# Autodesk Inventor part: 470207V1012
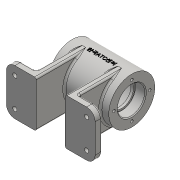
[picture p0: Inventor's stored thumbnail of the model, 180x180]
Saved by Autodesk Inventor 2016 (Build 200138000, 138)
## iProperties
Created: 2017-02
Part Number: 470207V1012
Material: 일반
Document SubType Name: Modeling
Designer: H
Density: 1 g/cm^3
Appearance: 기본값
Author: H
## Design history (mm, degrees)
sketch "스케치1"
  geometry: L1 (-35, 27)-(35, 27); L2 (35, 27)-(35, 0); L3 (35, 0)-(-35, 0); L4 (-35, 0)-(-35, 27); L5 (-70.456, 0)-(124.766, 0); 1 further point
  constraints: 10 end point, 2 horizontal, 2 parallel, 1 collinear, 1 perpendicular, 1 point on line
  dimensions: "d0" = 70 distance of L1.start L1.end; "d1" = 35 distance from line of L4 point (0, 0); "d2" = 27 distance of L1.end L2.end
revolve "회전1" sketch "스케치1" stored, may be unused: angle "d3" = 90 deg
sketch "스케치2"
  geometry: L1 (17, -52)-(52, -52); L2 (52, -52)-(52, -60); L3 (52, -60)-(17, -60); L4 (17, -60)-(17, -52); 1 further point
  constraints: 8 end point, 2 parallel, 1 horizontal, 1 perpendicular
  dimensions: "d4" = 35 distance of L2.end L3.end; "d5" = 8 distance of L1.end L2.end; "d6" = 17 distance from line of point (0, 0) L4; "d7" = 60 distance from line of L3 point (0, 0)
extrude "돌출1" join sketch "스케치2" stored distance "d8" = 54; taper "d9" = 0 deg
sketch "스케치3"
  geometry: L1 (17, 0)-(25, 0); L2 (25, 0)-(25, -60); L3 (25, -60)-(17, -60); L4 (17, -60)-(17, 0); L5 (17, -60)-(17, -52) reference; L6 (52, -60)-(17, -60) reference; 1 further point
  constraints: 8 end point, 2 collinear, 2 parallel, 1 horizontal, 1 perpendicular, 1 point on line
  dimensions: "d10" = 8 distance of L1.start L1.end
extrude "돌출2" join sketch "스케치3" stored distance "d12" = 54; taper "d13" = 0 deg
sketch "스케치4"
  geometry: L1 (-10, 44.214)-(-10, -7.125); L2 (-35, -27)-(-35, 27) reference; L3 (-15, 32)-(-10, 32); L4 (-10, 32)-(-10, 12); L5 (-10, 12)-(-15, 12); L6 (-15, 12)-(-15, 32); L7 (-35, 27)-(35, 27) reference; 1 further point
  constraints: 10 end point, 2 parallel, 1 collinear, 1 horizontal, 1 perpendicular, 1 vertical
  dimensions: "d14" = 25 distance between parallel lines of L1 L2; "d15" = 5 distance between parallel lines of L7 L3; "d16" = 5 distance of L3.start L3.end; "d17" = 20 distance of L5.end L3.start
revolve "회전2" sketch "스케치4" stored, may be unused: angle "d18" = 90 deg
sketch "스케치5"
  geometry: L1 (0, 0)-(-34.683, -22.523); L2 (0, 0)-(-46.212, 0); L3 (-8.387, -5.446)-(-25.16, -16.339); L4 (-25.16, -16.339)-(-21.892, -21.371); L5 (-21.892, -21.371)-(-5.119, -10.478); L6 (-5.119, -10.478)-(-8.387, -5.446); C1 r 27 at (0, 0) reference; 1 further point
  constraints: 12 end point, 2 parallel, 2 point on line, 1 horizontal, 1 perpendicular
  dimensions: "d19" = 33 deg angle of L2 L1; "d20" = 12 diameter of L5 L1; "d21" = 30 distance from line of L4 point (0, 0); "d22" = 20 distance between parallel lines of L4 L6
revolve "회전3" sketch "스케치5" stored, may be unused: angle "d23" = 90 deg
sketch "스케치6"
  geometry: C1 r 27 at (0, 0) reference; C2 r 16 at (0, 0); 1 further point
  constraints: 1 centre point, 1 coincident
  dimensions: "d24" = 32 diameter of C2
extrude "돌출3" cut sketch "스케치6" distance "d25" = 12; taper "d26" = 0 deg
sketch "스케치7"
  geometry: C1 r 14 at (0, 0); 1 further point
  constraints: 1 centre point, 1 coincident
  dimensions: "d27" = 28 diameter of C1
extrude "돌출4" cut sketch "스케치7" distance "d28" = 3; taper "d29" = 0 deg
sketch "스케치8"
  geometry: C1 r 22 at (0, 0); 1 further point
  constraints: 1 centre point, 1 coincident
  dimensions: "d30" = 44 diameter of C1
extrude "돌출5" cut sketch "스케치8" distance "d31" = 40; taper "d32" = 0 deg
sketch "스케치9"
  geometry: C1 r 5 at (0, 0) reference; 2 further points
  constraints: 1 coincident
hole "구멍1" sketch "스케치9" at (0, 0) diameter "d33" = 5.188; stored, may be unused: countersink angle "d37" = 90 deg, drill point angle "d39" = 118 deg; dims "d34" = 12, "d35" = 4, "d36" = 2, "d38" = 16
sketch "스케치10"
  geometry: C1 r 6 at (0, 0) reference; 2 further points
  constraints: 1 coincident
hole "구멍2" sketch "스케치10" at (0, 0) diameter "d40" = 5.188; stored, may be unused: countersink angle "d44" = 90 deg, drill point angle "d46" = 118 deg; dims "d41" = 12, "d42" = 4, "d43" = 2, "d45" = 16
sketch "스케치11"
  geometry: C1 r 27 at (0, 0) reference; 2 further points
  constraints: 1 vertical alignment
  dimensions: "d47" = 21 distance of point (0, 0) point (0, 21)
hole "구멍3" sketch "스케치11" at (0, 21) diameter "d48" = 3.242; stored, may be unused: countersink angle "d52" = 90 deg, drill point angle "d54" = 118 deg; dims "d49" = 8, "d50" = 4, "d51" = 2, "d53" = 10
fillet "모깎기1" dims "d58" = 10
sketch "스케치12"
  geometry: A1 r 10 centre (17, 10) between (17, 0) and (27, 10) reference; 2 further points
  constraints: 1 coincident
hole "구멍4" sketch "스케치12" at (17, 10) diameter "d59" = 5; stored, may be unused: countersink angle "d63" = 90 deg, drill point angle "d65" = 118 deg; dims "d60" = 8, "d61" = 4, "d62" = 2, "d64" = 10
fillet "모깎기2" dims "d75" = 0.3
fillet "모깎기3" dims "d76" = 2
fillet "모깎기4" dims "d77" = 2
fillet "모깎기5" dims "d78" = 2
fillet "모깎기6" dims "d79" = 2
chamfer "모따기1" distance "d80" = 1; stored, may be unused: second distance "d81" = 2, angle "d82" = 45 deg
chamfer "모따기2" distance "d83" = 1; stored, may be unused: second distance "d84" = 2, angle "d85" = 45 deg
fillet "모깎기7" dims "d86" = 2
fillet "모깎기8" dims "d87" = 3
node "작업 평면1"
sketch "스케치14"
  geometry: L1 (-35, 27)-(35, 27) reference; L2 (-35, -27)-(-35, 27) reference; 2 further points
  constraints: 1 other
  dimensions: "d89" = 27 distance from line of point (0, 0) L1; "d90" = 35 distance from line of L2 point (0, 0)
feature "엠보싱1" sketch "스케치14" dims "d91" = 0.5, "d92" = 0
sketch "스케치15" dims "d94" = 9
  geometry: L1 (12.402, 3.5)-(9.804, 8); L2 (9.804, 8)-(12.402, 12.5); L3 (12.402, 12.5)-(17.598, 12.5); L4 (17.598, 12.5)-(20.196, 8); L5 (20.196, 8)-(17.598, 3.5); L6 (17.598, 3.5)-(12.402, 3.5); C1 r 2.5 at (15, 8) reference; 4 further points
  constraints: 12 end point, 2 coincident, 1 midpoint, 1 vertical alignment, 15 other
extrude "돌출7" cut sketch "스케치15" distance "d95" = 3; taper "d96" = 0 deg
node "솔리드1"
mirror "대칭1"
mirror "대칭2"
pattern_circular "원형 패턴1" dims angle "d56" = 360 deg
mirror "대칭3"
pattern_linear "직사각형 패턴1" dims "d71" = 84, "d74" = 34
pattern_linear "직사각형 패턴2" dims "d99" = 34, "d102" = 84
other parameters: "d88" = 52.5
